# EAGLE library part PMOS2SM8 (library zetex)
Dual MOS FET
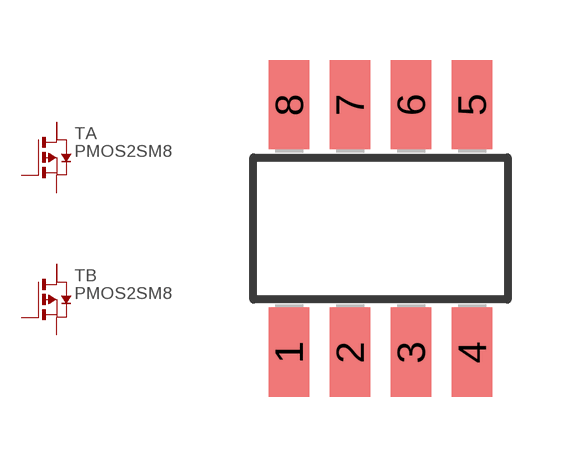
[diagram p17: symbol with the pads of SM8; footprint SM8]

Designator prefix T; gates A=P_MOS2D B=P_MOS2D

## PMOS2SM8 (MPN: STS1NK60Z; OC_FARNELL: 1412107; OC_NEWARK: 57P2212)  [SM8]
1  B:S  pas
2  B:G  pas
3  A:S  pas
4  A:G  pas
5  A:D  pas
6  A:D2  pas
7  B:D  pas
8  B:D2  pas

## Footprint SM8 (pad centres in mm)
SM8 Package
smd 1.016 x 2.235: 1 -2.286,-3.099; 2 -0.762,-3.099; 3 0.762,-3.099; 4 2.286,-3.099; 5 2.286,3.099; 6 0.762,3.099; 7 -0.762,3.099; 8 -2.286,3.099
